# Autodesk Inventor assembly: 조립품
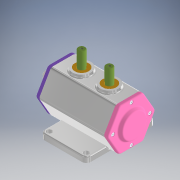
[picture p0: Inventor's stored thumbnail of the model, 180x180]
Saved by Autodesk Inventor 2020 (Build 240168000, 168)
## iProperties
Created: 2021-06
Part Number: 조립품
Document SubType Name: Assembly
Designer: 605-01
Author: 605-01
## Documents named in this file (11)
- C:\Users\605-01\Desktop\710606v1033\조립품.iam
- C:\Users\605-01\Desktop\710606v1033\본체.ipt
- C:\Users\605-01\Desktop\710606v1033\뒷커버.ipt
- C:\Users\605-01\Desktop\710606v1033\베어링 6203.ipt
- C:\Users\605-01\Desktop\710606v1033\베어링 6302.ipt
- C:\Users\605-01\Desktop\710606v1033\볼트 M4.ipt
- C:\Users\605-01\Desktop\710606v1033\부시.ipt
- C:\Users\605-01\Desktop\710606v1033\슬라이더.ipt
- C:\Users\605-01\Desktop\710606v1033\앞커버.ipt
- C:\Users\605-01\Desktop\710606v1033\오일실.ipt
- C:\Users\605-01\Desktop\710606v1033\편심축.ipt
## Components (10 placed, 3 different names)
1. 7-베어링 6203:1
2. 8-오일실:1
3. 9-M4-소켓머리:1 — 각도:2
4. 9-M4-소켓머리:3
5. 9-M4-소켓머리:4
6. 9-M4-소켓머리:5
7. 9-M4-소켓머리:2 — 각도:3
8. 9-M4-소켓머리:6
9. 9-M4-소켓머리:7
10. 9-M4-소켓머리:8
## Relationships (2: Angle 2)
- 각도:2 [Angle]: 9-M4-소켓머리:1
- 각도:3 [Angle]: 9-M4-소켓머리:2
